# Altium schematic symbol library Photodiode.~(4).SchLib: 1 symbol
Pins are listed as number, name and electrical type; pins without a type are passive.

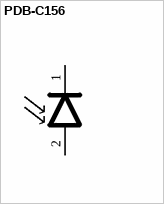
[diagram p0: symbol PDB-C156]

## PDB-C156
designator PD?  Supplier Part Number 1: PDB-C156-ND
Photodiode; Manufacturer: Used in BOM report; SymbolVersion: use current date i.e. 2008-05-20; SymbolCreator: Use LDAP id; CompType: Used in some BOM reports.  Useful for finding later.; U/M: EA, IN, or GM
footprint PDB-C156 (Photodiode)
pins: 1 C, 2 A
